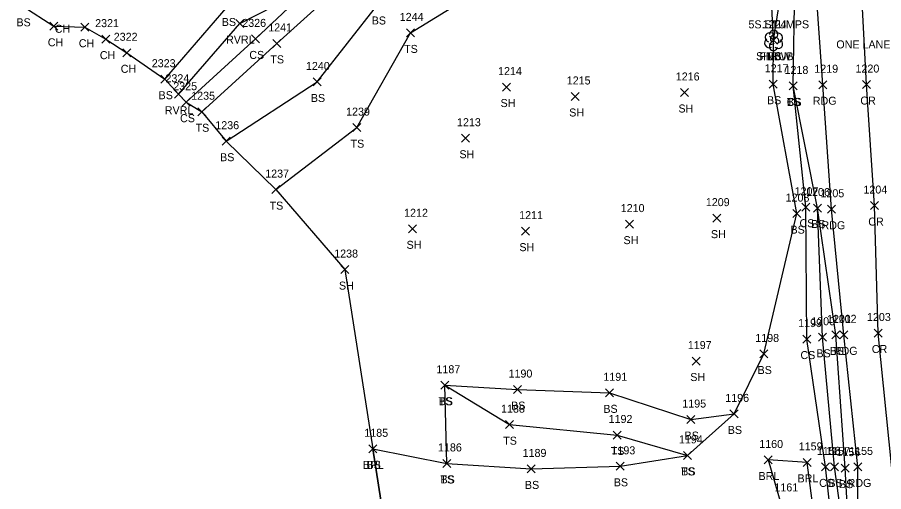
# Model space of a CAD drawing. Extents: x 1459992 to 1461532, y 647785 to 648535.
# Drawn here: x 1461179.9 to 1461396.4, y 647922.3 to 648040.8 of the extents above; entities that cross this region are included whole.
import ezdxf

# ---------------------------------------------------------------- set-up
doc = ezdxf.new("R2010")
doc.units = 0
for name, color, linetype in [('L_A', 7, 'Continuous'), ('L_C', 7, 'Continuous'), ('L_I', 7, 'Continuous'), ('L_TIC', 7, 'Continuous'), ('LABL', 7, 'Continuous'), ('LAWE', 7, 'Continuous'), ('LELB', 7, 'Continuous'), ('LFNC', 7, 'Continuous'), ('LSH', 7, 'Continuous'), ('LSOGP', 7, 'Continuous'), ('P_A', 7, 'Continuous'), ('P_I', 7, 'Continuous'), ('P_TIC', 7, 'Continuous'), ('PEU', 7, 'Continuous'), ('PRC', 7, 'Continuous'), ('S_C', 7, 'Continuous')]:
    doc.layers.add(name, color=color, linetype=linetype)

msp = doc.modelspace()

# ---------------------------------------------------------------- linework, layer by layer
at = {"layer": 'L_TIC'}
for points in [[(1461188.01, 648037.6), (1461190.01, 648039.6)], [(1461190.01, 648037.6), (1461188.01, 648039.6)], [(1461195.75, 648037.37), (1461197.75, 648039.37)], [(1461197.75, 648037.37), (1461195.75, 648039.37)], [(1461234.47, 648038.29), (1461236.47, 648040.29)], [(1461236.47, 648038.29), (1461234.47, 648040.29)], [(1461238.41, 648034.45), (1461240.41, 648036.45)], [(1461240.41, 648034.45), (1461238.41, 648036.45)], [(1461277.14, 648035.95), (1461279.14, 648037.95)], [(1461279.14, 648035.95), (1461277.14, 648037.95)], [(1461201.01, 648034.39), (1461203.01, 648036.39)], [(1461203.01, 648034.39), (1461201.01, 648036.39)], [(1461243.71, 648033.33), (1461245.71, 648035.33)], [(1461245.71, 648033.33), (1461243.71, 648035.33)], [(1461367.88, 648034.13), (1461369.88, 648036.13)], [(1461369.88, 648034.13), (1461367.88, 648036.13)], [(1461367.88, 648034.13), (1461369.88, 648036.13)], [(1461369.88, 648034.13), (1461367.88, 648036.13)], [(1461206.23, 648030.98), (1461208.23, 648032.98)], [(1461208.23, 648030.98), (1461206.23, 648032.98)], [(1461215.74, 648024.38), (1461217.74, 648026.38)], [(1461217.74, 648024.38), (1461215.74, 648026.38)], [(1461253.79, 648023.69), (1461255.79, 648025.69)], [(1461255.79, 648023.69), (1461253.79, 648025.69)], [(1461253.79, 648023.69), (1461255.79, 648025.69)], [(1461255.79, 648023.69), (1461253.79, 648025.69)], [(1461301.16, 648022.42), (1461303.16, 648024.42)], [(1461303.16, 648022.42), (1461301.16, 648024.42)], [(1461367.81, 648023.13), (1461369.81, 648025.13)], [(1461369.81, 648023.13), (1461367.81, 648025.13)], [(1461372.75, 648022.7), (1461374.75, 648024.7)], [(1461374.75, 648022.7), (1461372.75, 648024.7)], [(1461372.75, 648022.7), (1461374.75, 648024.7)], [(1461374.75, 648022.7), (1461372.75, 648024.7)], [(1461372.75, 648022.7), (1461374.75, 648024.7)], [(1461374.75, 648022.7), (1461372.75, 648024.7)], [(1461219.16, 648020.62), (1461221.16, 648022.62)], [(1461221.16, 648020.62), (1461219.16, 648022.62)], [(1461318.32, 648020.07), (1461320.32, 648022.07)], [(1461320.32, 648020.07), (1461318.32, 648022.07)], [(1461345.64, 648021.06), (1461347.64, 648023.06)], [(1461347.64, 648021.06), (1461345.64, 648023.06)], [(1461221.11, 648018.64), (1461223.11, 648020.64)], [(1461223.11, 648018.64), (1461221.11, 648020.64)], [(1461225.02, 648016.25), (1461227.02, 648018.25)], [(1461227.02, 648016.25), (1461225.02, 648018.25)], [(1461263.75, 648012.28), (1461265.75, 648014.28)], [(1461265.75, 648012.28), (1461263.75, 648014.28)], [(1461231.11, 648008.89), (1461233.11, 648010.89)], [(1461233.11, 648008.89), (1461231.11, 648010.89)], [(1461290.9, 648009.64), (1461292.9, 648011.64)], [(1461292.9, 648009.64), (1461290.9, 648011.64)], [(1461243.52, 647996.8), (1461245.52, 647998.8)], [(1461245.52, 647996.8), (1461243.52, 647998.8)], [(1461375.93, 647992.4), (1461377.93, 647994.4)], [(1461377.93, 647992.4), (1461375.93, 647994.4)], [(1461378.85, 647992.2), (1461380.85, 647994.2)], [(1461380.85, 647992.2), (1461378.85, 647994.2)], [(1461378.85, 647992.2), (1461380.85, 647994.2)], [(1461380.85, 647992.2), (1461378.85, 647994.2)], [(1461353.74, 647989.67), (1461355.74, 647991.67)], [(1461355.74, 647989.67), (1461353.74, 647991.67)], [(1461373.68, 647990.8), (1461375.68, 647992.8)], [(1461375.68, 647990.8), (1461373.68, 647992.8)], [(1461373.68, 647990.8), (1461375.68, 647992.8)], [(1461375.68, 647990.8), (1461373.68, 647992.8)], [(1461277.67, 647987.01), (1461279.67, 647989.01)], [(1461279.67, 647987.01), (1461277.67, 647989.01)], [(1461331.9, 647988.18), (1461333.9, 647990.18)], [(1461333.9, 647988.18), (1461331.9, 647990.18)], [(1461305.87, 647986.42), (1461307.87, 647988.42)], [(1461307.87, 647986.42), (1461305.87, 647988.42)], [(1461260.77, 647976.82), (1461262.77, 647978.82)], [(1461262.77, 647976.82), (1461260.77, 647978.82)], [(1461376.17, 647959.46), (1461378.17, 647961.46)], [(1461378.17, 647959.46), (1461376.17, 647961.46)], [(1461380.16, 647959.91), (1461382.16, 647961.91)], [(1461382.16, 647959.91), (1461380.16, 647961.91)], [(1461383.47, 647960.49), (1461385.47, 647962.49)], [(1461385.47, 647960.49), (1461383.47, 647962.49)], [(1461365.45, 647955.74), (1461367.45, 647957.74)], [(1461367.45, 647955.74), (1461365.45, 647957.74)], [(1461348.58, 647953.97), (1461350.58, 647955.97)], [(1461350.58, 647953.97), (1461348.58, 647955.97)], [(1461285.75, 647947.92), (1461287.75, 647949.92)], [(1461287.75, 647947.92), (1461285.75, 647949.92)], [(1461285.75, 647947.92), (1461287.75, 647949.92)], [(1461287.75, 647947.92), (1461285.75, 647949.92)], [(1461303.86, 647946.84), (1461305.86, 647948.84)], [(1461305.86, 647946.84), (1461303.86, 647948.84)], [(1461326.91, 647946.03), (1461328.91, 647948.03)], [(1461328.91, 647946.03), (1461326.91, 647948.03)], [(1461347.21, 647939.35), (1461349.21, 647941.35)], [(1461349.21, 647939.35), (1461347.21, 647941.35)], [(1461358, 647940.76), (1461360, 647942.76)], [(1461360, 647940.76), (1461358, 647942.76)], [(1461358, 647940.76), (1461360, 647942.76)], [(1461360, 647940.76), (1461358, 647942.76)], [(1461301.91, 647938.08), (1461303.91, 647940.08)], [(1461303.91, 647938.08), (1461301.91, 647940.08)], [(1461328.79, 647935.49), (1461330.79, 647937.49)], [(1461330.79, 647935.49), (1461328.79, 647937.49)], [(1461267.72, 647932.04), (1461269.72, 647934.04)], [(1461269.72, 647932.04), (1461267.72, 647934.04)], [(1461267.72, 647932.04), (1461269.72, 647934.04)], [(1461269.72, 647932.04), (1461267.72, 647934.04)], [(1461286.2, 647928.39), (1461288.2, 647930.39)], [(1461288.2, 647928.39), (1461286.2, 647930.39)], [(1461286.2, 647928.39), (1461288.2, 647930.39)], [(1461288.2, 647928.39), (1461286.2, 647930.39)], [(1461346.36, 647930.4), (1461348.36, 647932.4)], [(1461348.36, 647930.4), (1461346.36, 647932.4)], [(1461346.36, 647930.4), (1461348.36, 647932.4)], [(1461348.36, 647930.4), (1461346.36, 647932.4)], [(1461366.57, 647929.25), (1461368.57, 647931.25)], [(1461368.57, 647929.25), (1461366.57, 647931.25)], [(1461376.32, 647928.66), (1461378.32, 647930.66)], [(1461378.32, 647928.66), (1461376.32, 647930.66)], [(1461307.3, 647927.02), (1461309.3, 647929.02)], [(1461309.3, 647927.02), (1461307.3, 647929.02)], [(1461329.51, 647927.67), (1461331.51, 647929.67)], [(1461331.51, 647927.67), (1461329.51, 647929.67)], [(1461380.84, 647927.53), (1461382.84, 647929.53)], [(1461382.84, 647927.53), (1461380.84, 647929.53)], [(1461383.16, 647927.51), (1461385.16, 647929.51)], [(1461385.16, 647927.51), (1461383.16, 647929.51)], [(1461385.79, 647927.22), (1461387.79, 647929.22)], [(1461387.79, 647927.22), (1461385.79, 647929.22)]]:
    msp.add_lwpolyline(points, dxfattribs=at)
at = {"layer": 'LABL'}
msp.add_lwpolyline([(1461378.29, 647803.48), (1461378.32, 647838.24), (1461380.9, 647876.17), (1461381.26, 647898.94), (1461377.32, 647929.66), (1461367.57, 647930.25), (1461370.71, 647919.4), (1461373.92, 647893.27), (1461367.2, 647870.92), (1461361.58, 647863.28), (1461349.25, 647847.7), (1461359.99, 647825.96), (1461363.61, 647811.96), (1461346.89, 647820.57), (1461330.91, 647835.59), (1461313.25, 647858.73), (1461293.4, 647870.77), (1461281.07, 647893.04), (1461272.57, 647908.45), (1461268.72, 647933.04)], dxfattribs=at)
at = {"layer": 'LAWE'}
msp.add_lwpolyline([(1461220.16, 648021.62), (1461235.47, 648039.29), (1461252.97, 648048.33), (1461267.66, 648064.22), (1461276.22, 648071.52), (1461288.83, 648087.7), (1461307.75, 648107.55), (1461316.99, 648127.78), (1461326.45, 648138.79), (1461334.87, 648155.88), (1461340.57, 648163.3), (1461349.8, 648178.34), (1461354.71, 648199.54), (1461353.8, 648220.98), (1461352.34, 648246.45), (1461354.08, 648262.22), (1461358.25, 648276.14), (1461371.39, 648295.38), (1461381.98, 648319.02), (1461394.18, 648330.62), (1461418.25, 648335.82), (1461440.86, 648338.79), (1461464.61, 648337.5), (1461486.39, 648342.47)], dxfattribs=at)
at = {"layer": 'LELB'}
for points in [[(1461216.74, 648025.38), (1461232.53, 648043.68), (1461249.11, 648052.7), (1461265.41, 648068.57), (1461273.18, 648074.77), (1461285.77, 648090.04), (1461304, 648110.19), (1461314.1, 648129.87), (1461321.79, 648141.88), (1461329.36, 648157.89), (1461338.08, 648167.02), (1461343.94, 648182.36), (1461347.49, 648202.69), (1461348.84, 648222.98), (1461349.52, 648245.94), (1461349.95, 648262.88), (1461353.5, 648277.37), (1461366.77, 648299.23), (1461380.28, 648319.06), (1461391.62, 648332.95), (1461418.6, 648338.96), (1461441.31, 648340.65), (1461465.69, 648340.73), (1461485.92, 648346.23)], [(1461254.79, 648024.69), (1461270.01, 648044.05), (1461286.66, 648058.61), (1461302.71, 648076.47), (1461318.86, 648092.87), (1461331.51, 648115.53), (1461340.27, 648126.53), (1461345.02, 648130.3), (1461347.54, 648139.28), (1461343.67, 648143.43), (1461340.69, 648153.02)], [(1461222.11, 648019.64), (1461239.41, 648035.45), (1461252.97, 648048.33), (1461269.63, 648062.75), (1461277.56, 648070.16), (1461291.7, 648084.24), (1461310.28, 648105.5), (1461323.64, 648123.88), (1461332.79, 648141.48), (1461336.75, 648150.82)], [(1461226.02, 648017.25), (1461244.71, 648034.33), (1461263.29, 648051.1), (1461279.3, 648066.08), (1461297.19, 648082.44), (1461309.73, 648099.72), (1461327.42, 648118.18), (1461335.22, 648128.81), (1461339.47, 648139.3)], [(1461244.52, 647997.8), (1461264.75, 648013.28), (1461278.14, 648036.95), (1461298.41, 648049.42), (1461313.12, 648068.26), (1461328.13, 648085.89), (1461340.87, 648106.28), (1461352.19, 648115.96), (1461353.79, 648121.43), (1461352.84, 648127.82), (1461347.21, 648120.38), (1461340.27, 648126.53)], [(1461374.68, 647991.8), (1461368.81, 648024.13), (1461368.88, 648035.13), (1461373.77, 648066.02), (1461370.92, 648080.02), (1461362.56, 648099.2), (1461360.62, 648108.74)], [(1461373.75, 648023.7), (1461374.22, 648048.93), (1461374.47, 648055.02), (1461376.18, 648060.79)], [(1461232.11, 648009.89), (1461254.79, 648024.69)], [(1461388.01, 647801.67), (1461388.9, 647837.9), (1461388.96, 647875.39), (1461388.57, 647896.96), (1461386.79, 647928.22), (1461384.47, 647961.49), (1461379.85, 647993.2), (1461373.75, 648023.7)], [(1461382.87, 647802.6), (1461382.77, 647837.91), (1461387.97, 647877.03), (1461385.24, 647898.57), (1461381.84, 647928.53), (1461377.17, 647960.46), (1461376.93, 647993.4), (1461373.75, 648023.7)], [(1461388.57, 647896.96), (1461384.16, 647928.51), (1461381.16, 647960.91), (1461379.85, 647993.2)], [(1461268.72, 647933.04), (1461287.2, 647929.39), (1461308.3, 647928.02), (1461330.51, 647928.67), (1461347.36, 647931.4), (1461359, 647941.76), (1461366.45, 647956.74), (1461374.68, 647991.8)], [(1461287.2, 647929.39), (1461286.75, 647948.92), (1461302.91, 647939.08), (1461329.79, 647936.49), (1461347.36, 647931.4)], [(1461286.75, 647948.92), (1461304.86, 647947.84), (1461327.91, 647947.03), (1461348.21, 647940.35), (1461359, 647941.76)]]:
    msp.add_lwpolyline(points, dxfattribs=at)
at = {"layer": 'LFNC'}
msp.add_lwpolyline([(1461368.88, 648035.13), (1461367.39, 648065.1), (1461365.6, 648074.34)], dxfattribs=at)
at = {"layer": 'LSH'}
msp.add_line((1461368.88, 648035.13), (1461368.88, 648035.13), dxfattribs=at)
msp.add_line((1461368.88, 648035.13), (1461368.88, 648035.13), dxfattribs=at)
msp.add_arc((1461368.92, 648036.56), 1.05, 335.5272, 180.9563, dxfattribs=at)
for centre, major_axis, ratio, start_param, end_param in [((1461368.08, 648035.79), (1.21, -0.51), 0.895232, 1.570796, 4.712389), ((1461368.67, 648035.58), (-0.208, -0.792), 0.645439, 3.141593, 6.283185), ((1461369.92, 648035.71), (-1.14, -0.48), 0.949671, 1.570796, 4.712389), ((1461367.79, 648034.42), (0.58, -1.04), 0.959034, 3.141593, 6.283185), ((1461368.42, 648034.38), (-0.625, -0.083), 0.423636, 0, 3.141593), ((1461369.38, 648034.96), (-0.5, 0.667), 0.989748, 3.141593, 6.283185), ((1461369.88, 648034.29), (-1.09, 0.79), 0.841452, 1.570796, 4.712389), ((1461368.88, 648033.63), (0.26, 1.06), 0.942809, 1.570796, 4.712389)]:
    msp.add_ellipse(centre, major_axis=major_axis, ratio=ratio, start_param=start_param, end_param=end_param, dxfattribs=at)
at = {"layer": 'LSOGP'}
msp.add_lwpolyline([(1461181.21, 648043.59), (1461189.01, 648038.6), (1461196.75, 648038.37), (1461202.01, 648035.39), (1461207.23, 648031.98), (1461216.74, 648025.38), (1461220.16, 648021.62), (1461222.11, 648019.64), (1461226.02, 648017.25), (1461232.11, 648009.89), (1461244.52, 647997.8), (1461261.77, 647977.82), (1461268.72, 647933.04), (1461272.57, 647908.45)], dxfattribs=at)
at = {"layer": 'P_TIC'}
for points in [[(1461380.21, 648023), (1461382.21, 648025)], [(1461382.21, 648023), (1461380.21, 648025)], [(1461391.15, 648023.04), (1461393.15, 648025.04)], [(1461393.15, 648023.04), (1461391.15, 648025.04)], [(1461382.38, 647991.89), (1461384.38, 647993.89)], [(1461384.38, 647991.89), (1461382.38, 647993.89)], [(1461393.12, 647992.81), (1461395.12, 647994.81)], [(1461395.12, 647992.81), (1461393.12, 647994.81)], [(1461394.01, 647960.97), (1461396.01, 647962.97)], [(1461396.01, 647960.97), (1461394.01, 647962.97)], [(1461385.45, 647960.52), (1461387.45, 647962.52)], [(1461387.45, 647960.52), (1461385.45, 647962.52)], [(1461388.91, 647927.52), (1461390.91, 647929.52)], [(1461390.91, 647927.52), (1461388.91, 647929.52)]]:
    msp.add_lwpolyline(points, dxfattribs=at)
at = {"layer": 'PEU'}
msp.add_lwpolyline([(1461390.51, 647801.3), (1461390.53, 647837.72), (1461390.8, 647875.02), (1461390.06, 647897.41), (1461389.91, 647928.52), (1461386.45, 647961.52), (1461383.38, 647992.89), (1461381.21, 648024), (1461378.9, 648057), (1461379.85, 648065.17), (1461378.22, 648080.01), (1461375.84, 648101.64), (1461371.39, 648120.78), (1461367.19, 648133.39), (1461361.39, 648144.72), (1461357.89, 648149.47), (1461353.74, 648153.76)], dxfattribs=at)
at = {"layer": 'PRC'}
msp.add_lwpolyline([(1461399.1, 647801.61), (1461400.2, 647838.19), (1461399.73, 647875.76), (1461399.54, 647898.4), (1461398.45, 647928.21), (1461395.01, 647961.97), (1461394.12, 647993.81), (1461392.15, 648024.04), (1461390.38, 648057.37), (1461388.52, 648080.66), (1461387.02, 648100.03), (1461383.87, 648115.79), (1461378.35, 648129.27), (1461372.21, 648140.65), (1461365.44, 648150.97), (1461358.13, 648158.61)], dxfattribs=at)

# ---------------------------------------------------------------- texts
at = {"layer": 'L_A'}
for s, p in [('BS', (1461268.45, 648039.05)), ('BS', (1461179.65, 648038.59)), ('CH', (1461189.24, 648036.98)), ('BS', (1461230.97, 648038.68)), ('CH', (1461187.49, 648033.6)), ('CH', (1461195.24, 648033.37)), ('RVRL', (1461232.04, 648034.29)), ('CH', (1461200.5, 648030.39)), ('CS', (1461237.85, 648030.45)), ('TS', (1461276.55, 648031.95)), ('SHRUB', (1461364.51, 648030.13)), ('FNBW', (1461365.35, 648030.13)), ('BS', (1461367.32, 648030.13)), ('TS', (1461243.12, 648029.33)), ('CH', (1461205.72, 648026.98)), ('BS', (1461215.18, 648020.38)), ('BS', (1461253.23, 648019.69)), ('BS', (1461253.23, 648019.69)), ('SH', (1461300.65, 648018.42)), ('SH', (1461345.12, 648017.06)), ('BS', (1461367.25, 648019.13)), ('TS', (1461372.16, 648018.7)), ('CS', (1461372.19, 648018.7)), ('BS', (1461372.19, 648018.7)), ('RVRL', (1461216.73, 648016.62)), ('SH', (1461317.81, 648016.07)), ('CS', (1461220.55, 648014.64)), ('TS', (1461224.43, 648012.25)), ('TS', (1461263.16, 648008.28)), ('BS', (1461230.55, 648004.89)), ('SH', (1461290.38, 648005.64)), ('TS', (1461242.93, 647992.8)), ('BS', (1461373.12, 647986.8)), ('BS', (1461373.12, 647986.8)), ('CS', (1461375.37, 647988.4)), ('BS', (1461378.29, 647988.2)), ('BS', (1461378.29, 647988.2)), ('SH', (1461353.23, 647985.67)), ('SH', (1461277.16, 647983.01)), ('SH', (1461305.36, 647982.42)), ('SH', (1461331.39, 647984.18)), ('SH', (1461260.26, 647972.82)), ('BS', (1461382.91, 647956.49)), ('CS', (1461375.61, 647955.46)), ('BS', (1461379.6, 647955.91)), ('SH', (1461348.07, 647949.97)), ('BS', (1461364.89, 647951.74)), ('TS', (1461285.16, 647943.92)), ('BS', (1461285.19, 647943.92)), ('BS', (1461303.3, 647942.84)), ('BS', (1461326.35, 647942.03)), ('BS', (1461346.65, 647935.35)), ('BS', (1461357.44, 647936.76)), ('BS', (1461357.44, 647936.76)), ('TS', (1461301.32, 647934.08)), ('TS', (1461328.19, 647931.49)), ('BRL', (1461266.26, 647928.04)), ('BS', (1461267.16, 647928.04)), ('TS', (1461345.77, 647926.4)), ('BS', (1461345.8, 647926.4)), ('TS', (1461285.61, 647924.39)), ('BS', (1461285.64, 647924.39)), ('BRL', (1461365.12, 647925.25)), ('BRL', (1461374.87, 647924.66)), ('BS', (1461306.74, 647923.02)), ('BS', (1461328.95, 647923.67)), ('CS', (1461380.28, 647923.53)), ('BS', (1461382.6, 647923.51)), ('BS', (1461385.23, 647923.22))]:
    msp.add_text(s, height=2, dxfattribs=at).set_placement(p)
at = {"layer": 'L_C'}
msp.add_text('5S.STUMPS', height=2, dxfattribs=at).set_placement((1461362.61, 648038.09))
at = {"layer": 'L_I'}
for s, p in [('1244', (1461275.45, 648039.95)), ('2321', (1461199.32, 648038.39)), ('2326', (1461236.1, 648038.45)), ('1241', (1461242.59, 648037.33)), ('1224', (1461366.18, 648038.13)), ('1224', (1461366.18, 648038.13)), ('1224', (1461366.18, 648038.13)), ('2322', (1461203.97, 648034.98)), ('2323', (1461213.48, 648028.38)), ('1240', (1461252.01, 648027.69)), ('1240', (1461252.01, 648027.69)), ('1214', (1461300.03, 648026.42)), ('1217', (1461366.68, 648027.13)), ('1218', (1461371.63, 648026.7)), ('1218', (1461371.63, 648026.7)), ('1218', (1461371.63, 648026.7)), ('2324', (1461216.9, 648024.62)), ('1215', (1461317.2, 648024.07)), ('1216', (1461344.45, 648025.06)), ('2325', (1461218.85, 648022.64)), ('1235', (1461223.33, 648020.25)), ('1239', (1461262.05, 648016.28)), ('1236', (1461229.36, 648012.89)), ('1213', (1461289.77, 648013.64)), ('1237', (1461241.83, 648000.8)), ('1207', (1461374.15, 647996.4)), ('1206', (1461377.02, 647996.2)), ('1206', (1461377.02, 647996.2)), ('1209', (1461351.96, 647993.67)), ('1208', (1461371.9, 647994.8)), ('1208', (1461371.9, 647994.8)), ('1210', (1461330.69, 647992.18)), ('1212', (1461276.55, 647991.01)), ('1211', (1461305.31, 647990.42)), ('1238', (1461259.08, 647980.82)), ('1199', (1461375.04, 647963.46)), ('1200', (1461378.3, 647963.91)), ('1201', (1461382.27, 647964.49)), ('1198', (1461364.32, 647959.74)), ('1197', (1461347.46, 647957.97)), ('1187', (1461284.63, 647951.92)), ('1187', (1461284.63, 647951.92)), ('1190', (1461302.65, 647950.84)), ('1191', (1461326.35, 647950.03)), ('1196', (1461356.82, 647944.76)), ('1196', (1461356.82, 647944.76)), ('1188', (1461300.78, 647942.08)), ('1195', (1461346.08, 647943.35)), ('1192', (1461327.66, 647939.49)), ('1185', (1461266.6, 647936.04)), ('1185', (1461266.6, 647936.04)), ('1194', (1461345.24, 647934.4)), ('1194', (1461345.24, 647934.4)), ('1160', (1461365.31, 647933.25)), ('1159', (1461375.19, 647932.66)), ('1186', (1461285.02, 647932.39)), ('1186', (1461285.02, 647932.39)), ('1189', (1461306.17, 647931.02)), ('1193', (1461328.38, 647931.67)), ('1158', (1461379.72, 647931.53)), ('1157', (1461382.03, 647931.51)), ('1156', (1461384.61, 647931.22)), ('1161', (1461369.1, 647922.4)), ('1161', (1461369.1, 647922.4))]:
    msp.add_text(s, height=2, dxfattribs=at).set_placement(p)
at = {"layer": 'P_A'}
for s, p in [('RDG', (1461378.7, 648019)), ('CR', (1461390.58, 648019.04)), ('RDG', (1461380.87, 647987.89)), ('CR', (1461392.56, 647988.81)), ('RDG', (1461383.94, 647956.52)), ('CR', (1461393.45, 647956.97)), ('RDG', (1461387.4, 647923.52))]:
    msp.add_text(s, height=2, dxfattribs=at).set_placement(p)
at = {"layer": 'P_I'}
for s, p in [('1219', (1461379.08, 648027)), ('1220', (1461389.37, 648027.04)), ('1205', (1461380.61, 647995.89)), ('1204', (1461391.35, 647996.81)), ('1202', (1461383.68, 647964.52)), ('1203', (1461392.24, 647964.97)), ('1155', (1461387.79, 647931.52))]:
    msp.add_text(s, height=2, dxfattribs=at).set_placement(p)
at = {"layer": 'S_C'}
msp.add_text('ONE LANE BRIDGE, NO TRUCKS', height=2, dxfattribs=at).set_placement((1461384.58, 648033.08))

doc.saveas('drawing.dxf')
